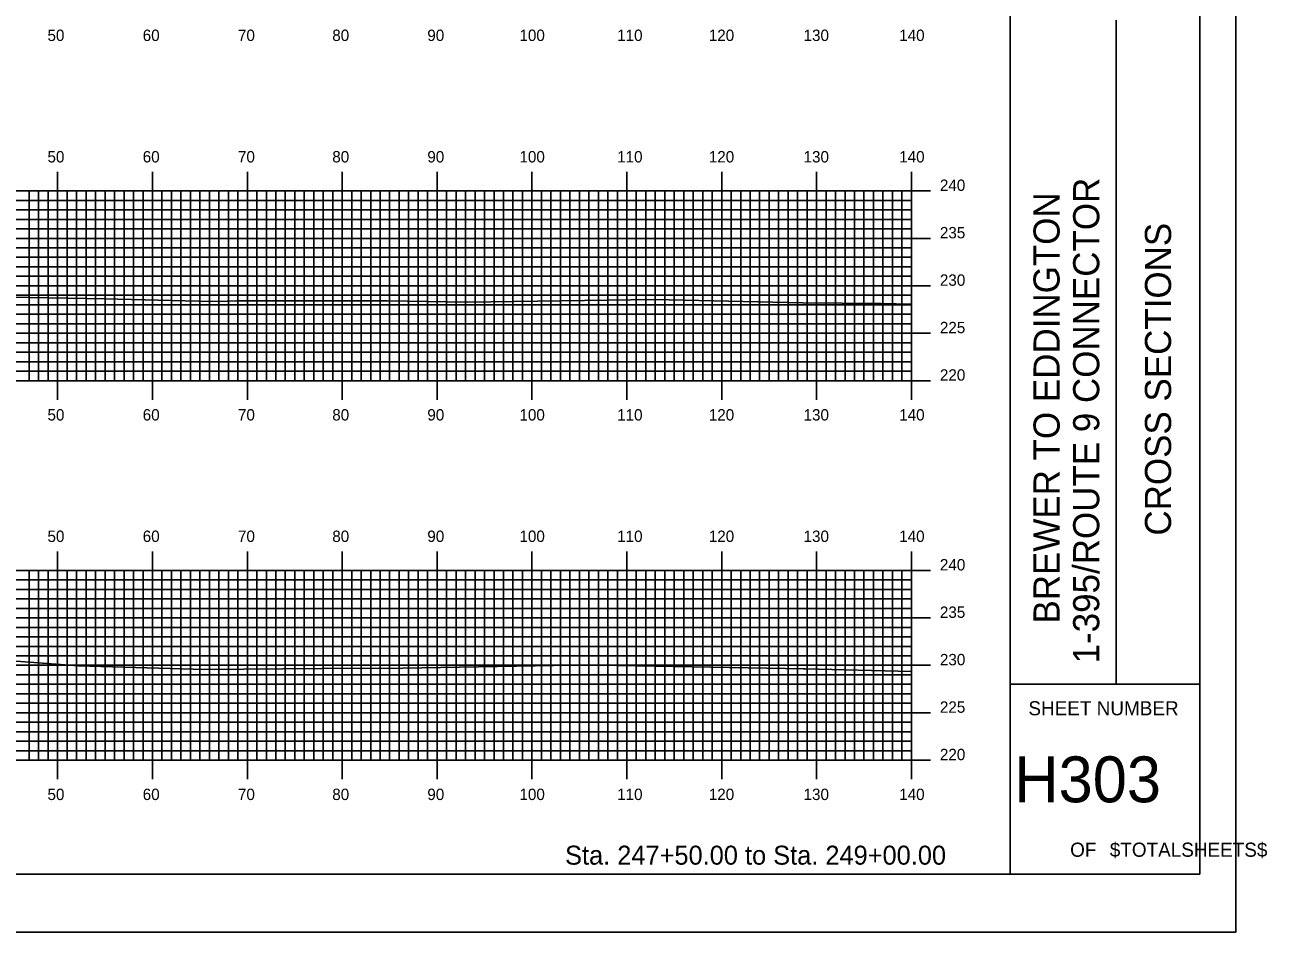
# Model space of a CAD drawing. Extents: x 1803503 to 1803847, y 442591 to 442811.
# Drawn here: x 1803715.7 to 1803846.6, y 442590.5 to 442686.2 of the extents above; entities that cross this region are included whole.
import ezdxf

# ---------------------------------------------------------------- set-up
doc = ezdxf.new("R2010")
doc.units = 0
for name, color, linetype in [('BORDER', 7, 'Continuous'), ('H_V ANNOTATION', 7, 'Continuous'), ('MAJOR', 7, 'Continuous'), ('MINOR', 7, 'Continuous'), ('PLOT BOUNDARY', 7, 'Continuous'), ('S_Roadway_Centerline', 7, 'Continuous')]:
    doc.layers.add(name, color=color, linetype=linetype)

msp = doc.modelspace()

# ---------------------------------------------------------------- linework, layer by layer
at = {"layer": 'BORDER'}
for p, q in [((1803819.54, 442596.67), (1803819.54, 442806.67)), ((1803830.72, 442616.67), (1803830.72, 442686.67)), ((1803819.54, 442616.67), (1803839.54, 442616.67))]:
    msp.add_line(p, q, dxfattribs=at)
msp.add_lwpolyline([(1803519.54, 442596.67), (1803839.54, 442596.67), (1803839.54, 442806.67), (1803519.54, 442806.67)], close=True, dxfattribs=at)
at = {"layer": 'MAJOR'}
for p, q in [((1803719.14, 442670.67), (1803719.14, 442668.67)), ((1803729.14, 442670.67), (1803729.14, 442668.67)), ((1803739.14, 442670.67), (1803739.14, 442668.67)), ((1803749.14, 442670.67), (1803749.14, 442668.67)), ((1803759.14, 442670.67), (1803759.14, 442668.67)), ((1803769.14, 442670.67), (1803769.14, 442668.67)), ((1803779.14, 442670.67), (1803779.14, 442668.67)), ((1803789.14, 442670.67), (1803789.14, 442668.67)), ((1803799.14, 442670.67), (1803799.14, 442668.67)), ((1803809.14, 442670.67), (1803809.14, 442668.67)), ((1803529.14, 442668.67), (1803809.14, 442668.67)), ((1803529.14, 442668.67), (1803809.14, 442668.67)), ((1803719.14, 442648.67), (1803719.14, 442668.67)), ((1803729.14, 442648.67), (1803729.14, 442668.67)), ((1803739.14, 442648.67), (1803739.14, 442668.67)), ((1803749.14, 442648.67), (1803749.14, 442668.67)), ((1803759.14, 442648.67), (1803759.14, 442668.67)), ((1803769.14, 442648.67), (1803769.14, 442668.67)), ((1803779.14, 442648.67), (1803779.14, 442668.67)), ((1803789.14, 442648.67), (1803789.14, 442668.67)), ((1803799.14, 442648.67), (1803799.14, 442668.67)), ((1803811.14, 442668.67), (1803807.14, 442668.67)), ((1803809.14, 442648.67), (1803809.14, 442668.67)), ((1803809.14, 442648.67), (1803809.14, 442668.67)), ((1803529.14, 442663.67), (1803809.14, 442663.67)), ((1803811.14, 442663.67), (1803807.14, 442663.67)), ((1803529.14, 442658.67), (1803809.14, 442658.67)), ((1803811.14, 442658.67), (1803807.14, 442658.67)), ((1803529.14, 442653.67), (1803809.14, 442653.67)), ((1803811.14, 442653.67), (1803807.14, 442653.67)), ((1803529.14, 442648.67), (1803809.14, 442648.67)), ((1803529.14, 442648.67), (1803809.14, 442648.67)), ((1803719.14, 442646.66), (1803719.14, 442648.67)), ((1803729.14, 442646.66), (1803729.14, 442648.67)), ((1803739.14, 442646.66), (1803739.14, 442648.67)), ((1803749.14, 442646.66), (1803749.14, 442648.67)), ((1803759.14, 442646.66), (1803759.14, 442648.67)), ((1803769.14, 442646.66), (1803769.14, 442648.67)), ((1803779.14, 442646.66), (1803779.14, 442648.67)), ((1803789.14, 442646.66), (1803789.14, 442648.67)), ((1803799.14, 442646.66), (1803799.14, 442648.67)), ((1803811.14, 442648.67), (1803807.14, 442648.67)), ((1803809.14, 442646.66), (1803809.14, 442648.67)), ((1803719.14, 442630.67), (1803719.14, 442628.67)), ((1803729.14, 442630.67), (1803729.14, 442628.67)), ((1803739.14, 442630.67), (1803739.14, 442628.67)), ((1803749.14, 442630.67), (1803749.14, 442628.67)), ((1803759.14, 442630.67), (1803759.14, 442628.67)), ((1803769.14, 442630.67), (1803769.14, 442628.67)), ((1803779.14, 442630.67), (1803779.14, 442628.67)), ((1803789.14, 442630.67), (1803789.14, 442628.67)), ((1803799.14, 442630.67), (1803799.14, 442628.67)), ((1803809.14, 442630.67), (1803809.14, 442628.67)), ((1803529.14, 442628.67), (1803809.14, 442628.67)), ((1803529.14, 442628.67), (1803809.14, 442628.67)), ((1803719.14, 442608.67), (1803719.14, 442628.67)), ((1803729.14, 442608.67), (1803729.14, 442628.67)), ((1803739.14, 442608.67), (1803739.14, 442628.67)), ((1803749.14, 442608.67), (1803749.14, 442628.67)), ((1803759.14, 442608.67), (1803759.14, 442628.67)), ((1803769.14, 442608.67), (1803769.14, 442628.67)), ((1803779.14, 442608.67), (1803779.14, 442628.67)), ((1803789.14, 442608.67), (1803789.14, 442628.67)), ((1803799.14, 442608.67), (1803799.14, 442628.67)), ((1803811.14, 442628.67), (1803807.14, 442628.67)), ((1803809.14, 442608.67), (1803809.14, 442628.67)), ((1803809.14, 442608.67), (1803809.14, 442628.67)), ((1803529.14, 442623.67), (1803809.14, 442623.67)), ((1803811.14, 442623.67), (1803807.14, 442623.67)), ((1803529.14, 442618.67), (1803809.14, 442618.67)), ((1803811.14, 442618.67), (1803807.14, 442618.67)), ((1803529.14, 442613.67), (1803809.14, 442613.67)), ((1803811.14, 442613.67), (1803807.14, 442613.67)), ((1803529.14, 442608.67), (1803809.14, 442608.67)), ((1803529.14, 442608.67), (1803809.14, 442608.67)), ((1803719.14, 442606.66), (1803719.14, 442608.67)), ((1803729.14, 442606.66), (1803729.14, 442608.67)), ((1803739.14, 442606.66), (1803739.14, 442608.67)), ((1803749.14, 442606.66), (1803749.14, 442608.67)), ((1803759.14, 442606.66), (1803759.14, 442608.67)), ((1803769.14, 442606.66), (1803769.14, 442608.67)), ((1803779.14, 442606.66), (1803779.14, 442608.67)), ((1803789.14, 442606.66), (1803789.14, 442608.67)), ((1803799.14, 442606.66), (1803799.14, 442608.67)), ((1803811.14, 442608.67), (1803807.14, 442608.67)), ((1803809.14, 442606.66), (1803809.14, 442608.67))]:
    msp.add_line(p, q, dxfattribs=at)
at = {"layer": 'MINOR'}
for p, q in [((1803716.14, 442648.67), (1803716.14, 442668.67)), ((1803717.14, 442648.67), (1803717.14, 442668.67)), ((1803718.14, 442648.67), (1803718.14, 442668.67)), ((1803720.14, 442648.67), (1803720.14, 442668.67)), ((1803721.14, 442648.67), (1803721.14, 442668.67)), ((1803722.14, 442648.67), (1803722.14, 442668.67)), ((1803723.14, 442648.67), (1803723.14, 442668.67)), ((1803724.14, 442648.67), (1803724.14, 442668.67)), ((1803725.14, 442648.67), (1803725.14, 442668.67)), ((1803726.14, 442648.67), (1803726.14, 442668.67)), ((1803727.14, 442648.67), (1803727.14, 442668.67)), ((1803728.14, 442648.67), (1803728.14, 442668.67)), ((1803730.14, 442648.67), (1803730.14, 442668.67)), ((1803731.14, 442648.67), (1803731.14, 442668.67)), ((1803732.14, 442648.67), (1803732.14, 442668.67)), ((1803733.14, 442648.67), (1803733.14, 442668.67)), ((1803734.14, 442648.67), (1803734.14, 442668.67)), ((1803735.14, 442648.67), (1803735.14, 442668.67)), ((1803736.14, 442648.67), (1803736.14, 442668.67)), ((1803737.14, 442648.67), (1803737.14, 442668.67)), ((1803738.14, 442648.67), (1803738.14, 442668.67)), ((1803740.14, 442648.67), (1803740.14, 442668.67)), ((1803741.14, 442648.67), (1803741.14, 442668.67)), ((1803742.14, 442648.67), (1803742.14, 442668.67)), ((1803743.14, 442648.67), (1803743.14, 442668.67)), ((1803744.14, 442648.67), (1803744.14, 442668.67)), ((1803745.14, 442648.67), (1803745.14, 442668.67)), ((1803746.14, 442648.67), (1803746.14, 442668.67)), ((1803747.14, 442648.67), (1803747.14, 442668.67)), ((1803748.14, 442648.67), (1803748.14, 442668.67)), ((1803750.14, 442648.67), (1803750.14, 442668.67)), ((1803751.14, 442648.67), (1803751.14, 442668.67)), ((1803752.14, 442648.67), (1803752.14, 442668.67)), ((1803753.14, 442648.67), (1803753.14, 442668.67)), ((1803754.14, 442648.67), (1803754.14, 442668.67)), ((1803755.14, 442648.67), (1803755.14, 442668.67)), ((1803756.14, 442648.67), (1803756.14, 442668.67)), ((1803757.14, 442648.67), (1803757.14, 442668.67)), ((1803758.14, 442648.67), (1803758.14, 442668.67)), ((1803760.14, 442648.67), (1803760.14, 442668.67)), ((1803761.14, 442648.67), (1803761.14, 442668.67)), ((1803762.14, 442648.67), (1803762.14, 442668.67)), ((1803763.14, 442648.67), (1803763.14, 442668.67)), ((1803764.14, 442648.67), (1803764.14, 442668.67)), ((1803765.14, 442648.67), (1803765.14, 442668.67)), ((1803766.14, 442648.67), (1803766.14, 442668.67)), ((1803767.14, 442648.67), (1803767.14, 442668.67)), ((1803768.14, 442648.67), (1803768.14, 442668.67)), ((1803770.14, 442648.67), (1803770.14, 442668.67)), ((1803771.14, 442648.67), (1803771.14, 442668.67)), ((1803772.14, 442648.67), (1803772.14, 442668.67)), ((1803773.14, 442648.67), (1803773.14, 442668.67)), ((1803774.14, 442648.67), (1803774.14, 442668.67)), ((1803775.14, 442648.67), (1803775.14, 442668.67)), ((1803776.14, 442648.67), (1803776.14, 442668.67)), ((1803777.14, 442648.67), (1803777.14, 442668.67)), ((1803778.14, 442648.67), (1803778.14, 442668.67)), ((1803780.14, 442648.67), (1803780.14, 442668.67)), ((1803781.14, 442648.67), (1803781.14, 442668.67)), ((1803782.14, 442648.67), (1803782.14, 442668.67)), ((1803783.14, 442648.67), (1803783.14, 442668.67)), ((1803784.14, 442648.67), (1803784.14, 442668.67)), ((1803785.14, 442648.67), (1803785.14, 442668.67)), ((1803786.14, 442648.67), (1803786.14, 442668.67)), ((1803787.14, 442648.67), (1803787.14, 442668.67)), ((1803788.14, 442648.67), (1803788.14, 442668.67)), ((1803790.14, 442648.67), (1803790.14, 442668.67)), ((1803791.14, 442648.67), (1803791.14, 442668.67)), ((1803792.14, 442648.67), (1803792.14, 442668.67)), ((1803793.14, 442648.67), (1803793.14, 442668.67)), ((1803794.14, 442648.67), (1803794.14, 442668.67)), ((1803795.14, 442648.67), (1803795.14, 442668.67)), ((1803796.14, 442648.67), (1803796.14, 442668.67)), ((1803797.14, 442648.67), (1803797.14, 442668.67)), ((1803798.14, 442648.67), (1803798.14, 442668.67)), ((1803800.14, 442648.67), (1803800.14, 442668.67)), ((1803801.14, 442648.67), (1803801.14, 442668.67)), ((1803802.14, 442648.67), (1803802.14, 442668.67)), ((1803803.14, 442648.67), (1803803.14, 442668.67)), ((1803804.14, 442648.67), (1803804.14, 442668.67)), ((1803805.14, 442648.67), (1803805.14, 442668.67)), ((1803806.14, 442648.67), (1803806.14, 442668.67)), ((1803807.14, 442648.67), (1803807.14, 442668.67)), ((1803808.14, 442648.67), (1803808.14, 442668.67)), ((1803529.14, 442667.67), (1803809.14, 442667.67)), ((1803809.14, 442667.67), (1803807.14, 442667.67)), ((1803529.14, 442666.67), (1803809.14, 442666.67)), ((1803529.14, 442665.67), (1803809.14, 442665.67)), ((1803809.14, 442666.67), (1803807.14, 442666.67)), ((1803809.14, 442665.67), (1803807.14, 442665.67)), ((1803529.14, 442664.67), (1803809.14, 442664.67)), ((1803809.14, 442664.67), (1803807.14, 442664.67)), ((1803529.14, 442662.67), (1803809.14, 442662.67)), ((1803529.14, 442661.67), (1803809.14, 442661.67)), ((1803809.14, 442662.67), (1803807.14, 442662.67)), ((1803809.14, 442661.67), (1803807.14, 442661.67)), ((1803529.14, 442660.67), (1803809.14, 442660.67)), ((1803809.14, 442660.67), (1803807.14, 442660.67)), ((1803529.14, 442659.67), (1803809.14, 442659.67)), ((1803809.14, 442659.67), (1803807.14, 442659.67)), ((1803529.14, 442657.67), (1803809.14, 442657.67)), ((1803809.14, 442657.67), (1803807.14, 442657.67)), ((1803529.14, 442656.67), (1803809.14, 442656.67)), ((1803809.14, 442656.67), (1803807.14, 442656.67)), ((1803529.14, 442655.67), (1803809.14, 442655.67)), ((1803809.14, 442655.67), (1803807.14, 442655.67)), ((1803529.14, 442654.67), (1803809.14, 442654.67)), ((1803809.14, 442654.67), (1803807.14, 442654.67)), ((1803529.14, 442652.67), (1803809.14, 442652.67)), ((1803809.14, 442652.67), (1803807.14, 442652.67)), ((1803529.14, 442651.67), (1803809.14, 442651.67)), ((1803809.14, 442651.67), (1803807.14, 442651.67)), ((1803529.14, 442650.67), (1803809.14, 442650.67)), ((1803809.14, 442650.67), (1803807.14, 442650.67)), ((1803529.14, 442649.67), (1803809.14, 442649.67)), ((1803809.14, 442649.67), (1803807.14, 442649.67)), ((1803529.14, 442627.67), (1803809.14, 442627.67)), ((1803716.14, 442608.67), (1803716.14, 442628.67)), ((1803717.14, 442608.67), (1803717.14, 442628.67)), ((1803718.14, 442608.67), (1803718.14, 442628.67)), ((1803720.14, 442608.67), (1803720.14, 442628.67)), ((1803721.14, 442608.67), (1803721.14, 442628.67)), ((1803722.14, 442608.67), (1803722.14, 442628.67)), ((1803723.14, 442608.67), (1803723.14, 442628.67)), ((1803724.14, 442608.67), (1803724.14, 442628.67)), ((1803725.14, 442608.67), (1803725.14, 442628.67)), ((1803726.14, 442608.67), (1803726.14, 442628.67)), ((1803727.14, 442608.67), (1803727.14, 442628.67)), ((1803728.14, 442608.67), (1803728.14, 442628.67)), ((1803730.14, 442608.67), (1803730.14, 442628.67)), ((1803731.14, 442608.67), (1803731.14, 442628.67)), ((1803732.14, 442608.67), (1803732.14, 442628.67)), ((1803733.14, 442608.67), (1803733.14, 442628.67)), ((1803734.14, 442608.67), (1803734.14, 442628.67)), ((1803735.14, 442608.67), (1803735.14, 442628.67)), ((1803736.14, 442608.67), (1803736.14, 442628.67)), ((1803737.14, 442608.67), (1803737.14, 442628.67)), ((1803738.14, 442608.67), (1803738.14, 442628.67)), ((1803740.14, 442608.67), (1803740.14, 442628.67)), ((1803741.14, 442608.67), (1803741.14, 442628.67)), ((1803742.14, 442608.67), (1803742.14, 442628.67)), ((1803743.14, 442608.67), (1803743.14, 442628.67)), ((1803744.14, 442608.67), (1803744.14, 442628.67)), ((1803745.14, 442608.67), (1803745.14, 442628.67)), ((1803746.14, 442608.67), (1803746.14, 442628.67)), ((1803747.14, 442608.67), (1803747.14, 442628.67)), ((1803748.14, 442608.67), (1803748.14, 442628.67)), ((1803750.14, 442608.67), (1803750.14, 442628.67)), ((1803751.14, 442608.67), (1803751.14, 442628.67)), ((1803752.14, 442608.67), (1803752.14, 442628.67)), ((1803753.14, 442608.67), (1803753.14, 442628.67)), ((1803754.14, 442608.67), (1803754.14, 442628.67)), ((1803755.14, 442608.67), (1803755.14, 442628.67)), ((1803756.14, 442608.67), (1803756.14, 442628.67)), ((1803757.14, 442608.67), (1803757.14, 442628.67)), ((1803758.14, 442608.67), (1803758.14, 442628.67)), ((1803760.14, 442608.67), (1803760.14, 442628.67)), ((1803761.14, 442608.67), (1803761.14, 442628.67)), ((1803762.14, 442608.67), (1803762.14, 442628.67)), ((1803763.14, 442608.67), (1803763.14, 442628.67)), ((1803764.14, 442608.67), (1803764.14, 442628.67)), ((1803765.14, 442608.67), (1803765.14, 442628.67)), ((1803766.14, 442608.67), (1803766.14, 442628.67)), ((1803767.14, 442608.67), (1803767.14, 442628.67)), ((1803768.14, 442608.67), (1803768.14, 442628.67)), ((1803770.14, 442608.67), (1803770.14, 442628.67)), ((1803771.14, 442608.67), (1803771.14, 442628.67)), ((1803772.14, 442608.67), (1803772.14, 442628.67)), ((1803773.14, 442608.67), (1803773.14, 442628.67)), ((1803774.14, 442608.67), (1803774.14, 442628.67)), ((1803775.14, 442608.67), (1803775.14, 442628.67)), ((1803776.14, 442608.67), (1803776.14, 442628.67)), ((1803777.14, 442608.67), (1803777.14, 442628.67)), ((1803778.14, 442608.67), (1803778.14, 442628.67)), ((1803780.14, 442608.67), (1803780.14, 442628.67)), ((1803781.14, 442608.67), (1803781.14, 442628.67)), ((1803782.14, 442608.67), (1803782.14, 442628.67)), ((1803783.14, 442608.67), (1803783.14, 442628.67)), ((1803784.14, 442608.67), (1803784.14, 442628.67)), ((1803785.14, 442608.67), (1803785.14, 442628.67)), ((1803786.14, 442608.67), (1803786.14, 442628.67)), ((1803787.14, 442608.67), (1803787.14, 442628.67)), ((1803788.14, 442608.67), (1803788.14, 442628.67)), ((1803790.14, 442608.67), (1803790.14, 442628.67)), ((1803791.14, 442608.67), (1803791.14, 442628.67)), ((1803792.14, 442608.67), (1803792.14, 442628.67)), ((1803793.14, 442608.67), (1803793.14, 442628.67)), ((1803794.14, 442608.67), (1803794.14, 442628.67)), ((1803795.14, 442608.67), (1803795.14, 442628.67)), ((1803796.14, 442608.67), (1803796.14, 442628.67)), ((1803797.14, 442608.67), (1803797.14, 442628.67)), ((1803798.14, 442608.67), (1803798.14, 442628.67)), ((1803800.14, 442608.67), (1803800.14, 442628.67)), ((1803801.14, 442608.67), (1803801.14, 442628.67)), ((1803802.14, 442608.67), (1803802.14, 442628.67)), ((1803803.14, 442608.67), (1803803.14, 442628.67)), ((1803804.14, 442608.67), (1803804.14, 442628.67)), ((1803805.14, 442608.67), (1803805.14, 442628.67)), ((1803806.14, 442608.67), (1803806.14, 442628.67)), ((1803807.14, 442608.67), (1803807.14, 442628.67)), ((1803809.14, 442627.67), (1803807.14, 442627.67)), ((1803808.14, 442608.67), (1803808.14, 442628.67)), ((1803529.14, 442626.67), (1803809.14, 442626.67)), ((1803809.14, 442626.67), (1803807.14, 442626.67)), ((1803529.14, 442625.67), (1803809.14, 442625.67)), ((1803809.14, 442625.67), (1803807.14, 442625.67)), ((1803529.14, 442624.67), (1803809.14, 442624.67)), ((1803809.14, 442624.67), (1803807.14, 442624.67)), ((1803529.14, 442622.67), (1803809.14, 442622.67)), ((1803809.14, 442622.67), (1803807.14, 442622.67)), ((1803529.14, 442621.67), (1803809.14, 442621.67)), ((1803809.14, 442621.67), (1803807.14, 442621.67)), ((1803529.14, 442620.67), (1803809.14, 442620.67)), ((1803529.14, 442619.67), (1803809.14, 442619.67)), ((1803809.14, 442620.67), (1803807.14, 442620.67)), ((1803809.14, 442619.67), (1803807.14, 442619.67)), ((1803529.14, 442617.67), (1803809.14, 442617.67)), ((1803809.14, 442617.67), (1803807.14, 442617.67)), ((1803529.14, 442616.67), (1803809.14, 442616.67)), ((1803809.14, 442616.67), (1803807.14, 442616.67)), ((1803529.14, 442615.67), (1803809.14, 442615.67)), ((1803529.14, 442614.67), (1803809.14, 442614.67)), ((1803809.14, 442615.67), (1803807.14, 442615.67)), ((1803809.14, 442614.67), (1803807.14, 442614.67)), ((1803529.14, 442612.67), (1803809.14, 442612.67)), ((1803809.14, 442612.67), (1803807.14, 442612.67)), ((1803529.14, 442611.67), (1803809.14, 442611.67)), ((1803529.14, 442610.67), (1803809.14, 442610.67)), ((1803809.14, 442611.67), (1803807.14, 442611.67)), ((1803809.14, 442610.67), (1803807.14, 442610.67)), ((1803529.14, 442609.67), (1803809.14, 442609.67)), ((1803809.14, 442609.67), (1803807.14, 442609.67))]:
    msp.add_line(p, q, dxfattribs=at)
at = {"layer": 'PLOT BOUNDARY'}
msp.add_lwpolyline([(1803503.35, 442590.55), (1803843.35, 442590.55), (1803843.35, 442810.55), (1803503.35, 442810.55)], close=True, dxfattribs=at)
at = {"layer": 'S_Roadway_Centerline'}
for points in [[(1803714.08, 442657.48), (1803724.07, 442657.31), (1803733.99, 442657.05), (1803736, 442657.01), (1803738.02, 442657.1), (1803753.86, 442657.09), (1803762.33, 442656.93), (1803782.06, 442657.23), (1803797.64, 442656.87), (1803805.96, 442656.8), (1803809.14, 442656.74)], [(1803714.28, 442619.15), (1803721.29, 442618.63), (1803734.64, 442618.23), (1803747, 442618.34), (1803755.53, 442618.36), (1803773.46, 442618.67), (1803775.01, 442618.69), (1803776.17, 442618.68), (1803795.88, 442618.33), (1803797.73, 442618.3), (1803797.94, 442618.3), (1803809.14, 442618.03)]]:
    msp.add_lwpolyline(points, dxfattribs=at)

# ---------------------------------------------------------------- texts
at = {"layer": 'BORDER'}
for s, p in [('1-395/ROUTE 9 CONNECTOR', (1803828.94, 442618.87)), ('BREWER TO EDDINGTON', (1803824.76, 442623.07)), ('CROSS SECTIONS', (1803836.51, 442632.34))]:
    msp.add_text(s, height=2.7557, rotation=90, dxfattribs=at).set_placement(p)
for s, height, p in [('SHEET NUMBER', 1.4905, (1803821.47, 442613.4)), ('H303', 4.839, (1803819.98, 442604.23)), ('OF', 1.491, (1803825.87, 442598.49)), ('$TOTALSHEETS$', 1.4905, (1803830.05, 442598.49))]:
    msp.add_text(s, height=height, dxfattribs=at).set_placement(p)
at = {"layer": 'H_V ANNOTATION'}
for s, height, p in [('50', 1.2, (1803718.07, 442684.47)), ('60', 1.2, (1803728.11, 442684.47)), ('70', 1.2, (1803738.15, 442684.47)), ('80', 1.2, (1803748.09, 442684.47)), ('90', 1.2, (1803758.11, 442684.47)), ('100', 1.2, (1803767.82, 442684.47)), ('110', 1.2, (1803778.12, 442684.47)), ('120', 1.2, (1803787.78, 442684.47)), ('130', 1.2, (1803797.77, 442684.47)), ('140', 1.2, (1803807.85, 442684.47)), ('50', 1.2, (1803718.07, 442671.67)), ('60', 1.2, (1803728.11, 442671.67)), ('70', 1.2, (1803738.15, 442671.67)), ('80', 1.2, (1803748.09, 442671.67)), ('90', 1.2, (1803758.11, 442671.67)), ('100', 1.2, (1803767.82, 442671.67)), ('110', 1.2, (1803778.12, 442671.67)), ('120', 1.2, (1803787.78, 442671.67)), ('130', 1.2, (1803797.77, 442671.67)), ('140', 1.2, (1803807.85, 442671.67)), ('240', 1.2, (1803812.14, 442668.67)), ('235', 1.2, (1803812.14, 442663.67)), ('230', 1.2, (1803812.14, 442658.67)), ('225', 1.2, (1803812.14, 442653.67)), ('220', 1.2, (1803812.14, 442648.67)), ('50', 1.2, (1803718.07, 442644.47)), ('60', 1.2, (1803728.11, 442644.47)), ('70', 1.2, (1803738.15, 442644.47)), ('80', 1.2, (1803748.09, 442644.47)), ('90', 1.2, (1803758.11, 442644.47)), ('100', 1.2, (1803767.82, 442644.47)), ('110', 1.2, (1803778.12, 442644.47)), ('120', 1.2, (1803787.78, 442644.47)), ('130', 1.2, (1803797.77, 442644.47)), ('140', 1.2, (1803807.85, 442644.47)), ('50', 1.2, (1803718.07, 442631.67)), ('60', 1.2, (1803728.11, 442631.67)), ('70', 1.2, (1803738.15, 442631.67)), ('80', 1.2, (1803748.09, 442631.67)), ('90', 1.2, (1803758.11, 442631.67)), ('100', 1.2, (1803767.82, 442631.67)), ('110', 1.2, (1803778.12, 442631.67)), ('120', 1.2, (1803787.78, 442631.67)), ('130', 1.2, (1803797.77, 442631.67)), ('140', 1.2, (1803807.85, 442631.67)), ('240', 1.2, (1803812.14, 442628.67)), ('235', 1.2, (1803812.14, 442623.67)), ('230', 1.2, (1803812.14, 442618.67)), ('225', 1.2, (1803812.14, 442613.67)), ('220', 1.2, (1803812.14, 442608.67)), ('50', 1.2, (1803718.07, 442604.47)), ('60', 1.2, (1803728.11, 442604.47)), ('70', 1.2, (1803738.15, 442604.47)), ('80', 1.2, (1803748.09, 442604.47)), ('90', 1.2, (1803758.11, 442604.47)), ('100', 1.2, (1803767.82, 442604.47)), ('110', 1.2, (1803778.12, 442604.47)), ('120', 1.2, (1803787.78, 442604.47)), ('130', 1.2, (1803797.77, 442604.47)), ('140', 1.2, (1803807.85, 442604.47)), ('Sta. 247+50.00 to Sta. 249+00.00', 2.0004, (1803772.63, 442597.66))]:
    msp.add_text(s, height=height, dxfattribs=at).set_placement(p)

doc.saveas('drawing.dxf')
